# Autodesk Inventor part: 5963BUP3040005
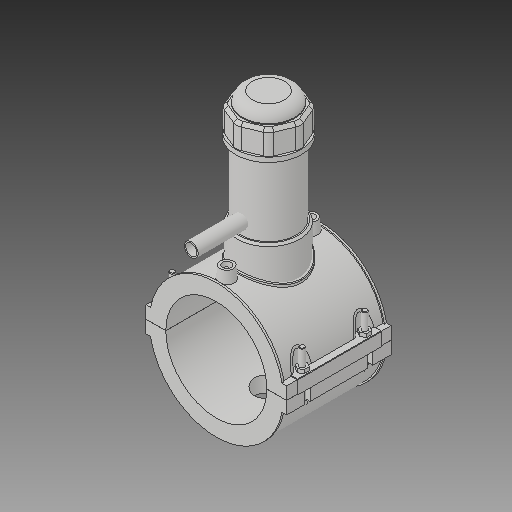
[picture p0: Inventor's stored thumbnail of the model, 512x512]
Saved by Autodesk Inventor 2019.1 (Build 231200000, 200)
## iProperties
Created: 2017-07
Part Number: 5963BUP3040005
Material: Generic
Description: PLASSON TAPPING SADDLE 4''IPS x 1/2''CTS
Document SubType Name: Modeling
Designer: KIM
Density: 1 g/cm^3
Appearance: Default
Author: KIM
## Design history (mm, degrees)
derived "5963BBP_5963BUP.ipt"
feature "Solid1::5963BBP_5963BUP.ipt"
feature "Solid2::5963BBP_5963BUP.ipt"
feature "Solid3::5963BBP_5963BUP.ipt"
tag "TaggingFeature1"
body "Solid1"
body "Solid2"
body "Solid3"
other parameters: "d0" = 114.1, "d2" = 159.004, "d3" = 28.525, "d4" = 118.11, "d5" = 0, "d6" = 0.1, "d8" = 0, "d19" = 6, "d20" = 6, "d21" = 70.866, "d23" = 0, "d24" = 35.433, "d26" = 0, "d27" = 3, "d28" = 3, "d29" = 3, "d30" = 38.03333, "d31" = 6, "d32" = 0, "d33" = 0, "d34" = 0.6, "d40" = 77.1316, "d41" = 74.165, "d43" = 0, "d45" = 0, "d47" = 145.031, "d70" = 15, "d72" = 0, "d73" = 6, "d75" = 5, "d76" = 0, "d77" = 5.705, "d78" = 87.05, "d79" = 15, "d80" = 47.244, "d82" = 5 deg, "d84" = 4, "d85" = 14, "d86" = 0, "d87" = 3, "d88" = 0, "d89" = 1, "d90" = 1, "d91" = 94.488, "d92" = 0, "d93" = 0.5, "d94" = 60.05263, "d96" = 151.2966, "d97" = 2.3622, "d98" = 0, "d102" = 1.141, "d120" = 140 deg, "d121" = 24.228, "d122" = 20 deg, "d123" = 296.66, "d124" = 88.998, "d126" = 0, "d143" = 117.523, "d145" = 26.33077, "d149" = 1.7115, "d150" = 28.96385, "d153" = 118.11, "d154" = 0, "d156" = 74.165, "d157" = 160 deg, "d159" = 6.846, "d161" = 1.7115, "d162" = 70.866, "d163" = 0, "d164" = 57.05, "d167" = 11.41, "d168" = 72.3561, "d170" = 3.2805, "d172" = 0, "d173" = 1, "d175" = 57.05, "d176" = 20 deg, "d177" = 7.987, "d178" = 34.23, "d180" = 0, "d183" = 13.692, "d184" = 6.3896, "d185" = 38.38575, "d186" = 38.38575, "d187" = 74.165, "d188" = 10.269, "d189" = 7.987, "d190" = 0, "d191" = 111.2475, "d193" = 6.9984, "d194" = 4.13385, "d195" = 90 deg, "d197" = 0, "d199" = 0, "d200" = 17.115, "d202" = 0, "d203" = 177.038, "d204" = 70.45675, "d205" = 51.9155, "d206" = 63.04025, "d207" = 132.7785, "d208" = 138.08964, "d209" = 164.64534, "d210" = 63.7819, "d211" = 74.165, "d212" = 59.332, "d213" = 51.4116, "d216" = 0, "d217" = 11.41, "d218" = 11.41, "d219" = 2.282, "d222" = 114.1, "d224" = 0, "d225" = 65.024, "d226" = 15.8, "d227" = 12.64, "d228" = 87.376, "d230" = 3.423, "d_" = 114.1, "B_" = 159.004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
